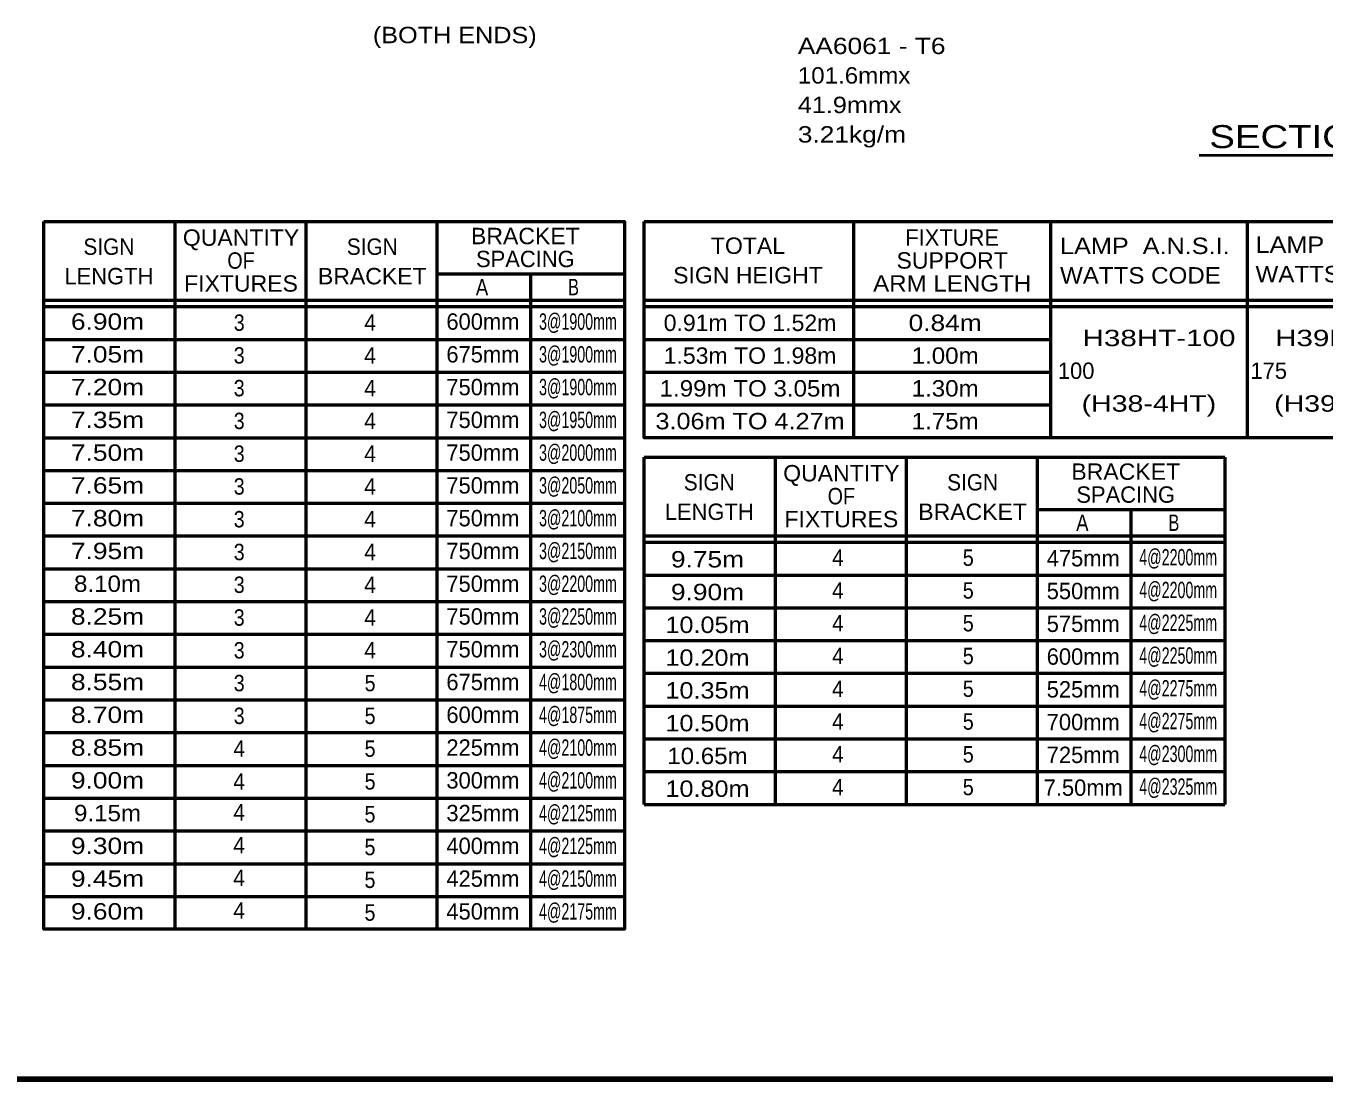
# Model space of a CAD drawing. Extents: x -94 to 762, y -50 to 494.
# Drawn here: x 194.5 to 432, y -38.7 to 154.1 of the extents above; entities that cross this region are included whole.
import ezdxf
from ezdxf.enums import TextEntityAlignment as Align

# ---------------------------------------------------------------- set-up
doc = ezdxf.new("R2010")
doc.units = 0
doc.header["$LTSCALE"] = 1.2
doc.layers.add('1', color=7, linetype='Continuous', lineweight=53)

msp = doc.modelspace()

# ---------------------------------------------------------------- linework, layer by layer
at = {"layer": '1', "lineweight": 40}
msp.add_line((409.176, 130.418), (466.375, 130.418), dxfattribs=at)
at = {"layer": '1'}
for p, q in [((221.733, -11.296), (221.733, 118.303)), ((245.733, -11.296), (245.733, 118.303)), ((269.733, -11.296), (269.733, 118.303)), ((346.014, 78.704), (346.014, 118.303)), ((382.014, 78.704), (382.014, 118.303)), ((418.014, 78.704), (418.014, 118.303)), ((269.733, 108.704), (304.014, 108.704)), ((286.873, -11.296), (286.873, 108.704)), ((197.733, 103.904), (304.014, 103.904)), ((197.733, 102.704), (304.014, 102.704)), ((307.614, 103.904), (490.014, 103.904)), ((307.614, 102.704), (490.014, 102.704)), ((197.733, 96.704), (304.014, 96.704)), ((307.614, 96.704), (382.014, 96.704)), ((197.733, 90.704), (304.014, 90.704)), ((307.614, 90.704), (382.014, 90.704)), ((197.733, 84.704), (304.014, 84.704)), ((307.614, 84.704), (382.014, 84.704)), ((197.733, 78.704), (304.014, 78.704)), ((307.617, 75.162), (379.617, 75.162)), ((307.617, 11.562), (307.617, 75.162)), ((331.617, 11.562), (331.617, 75.162)), ((355.617, 11.562), (355.617, 75.162)), ((379.617, 11.562), (379.617, 75.162)), ((379.617, 75.162), (413.899, 75.162)), ((413.899, 75.162), (413.899, 11.562)), ((197.733, 72.704), (304.014, 72.704)), ((197.733, 66.704), (304.014, 66.704)), ((379.617, 65.562), (413.899, 65.562)), ((396.758, 11.562), (396.758, 65.562)), ((197.733, 60.704), (304.014, 60.704)), ((307.617, 60.762), (379.617, 60.762)), ((307.617, 59.562), (379.617, 59.562)), ((379.617, 60.762), (413.899, 60.762)), ((379.617, 59.562), (413.899, 59.562)), ((197.733, 54.704), (304.014, 54.704)), ((307.617, 53.562), (379.617, 53.562)), ((379.617, 53.562), (413.899, 53.562)), ((197.733, 48.704), (304.014, 48.704)), ((307.617, 47.562), (379.617, 47.562)), ((379.617, 47.562), (413.899, 47.562)), ((197.733, 42.704), (304.014, 42.704)), ((307.617, 41.562), (379.617, 41.562)), ((379.617, 41.562), (413.899, 41.562)), ((197.733, 36.703), (304.014, 36.703)), ((307.617, 35.562), (379.617, 35.562)), ((379.617, 35.562), (413.899, 35.562)), ((197.733, 30.704), (304.014, 30.704)), ((307.617, 29.562), (379.617, 29.562)), ((379.617, 29.562), (413.899, 29.562)), ((197.733, 24.704), (304.014, 24.704)), ((307.617, 23.562), (379.617, 23.562)), ((379.617, 23.562), (413.899, 23.562)), ((197.733, 18.704), (304.014, 18.704)), ((307.617, 17.562), (379.617, 17.562)), ((379.617, 17.562), (413.899, 17.562)), ((197.733, 12.704), (304.014, 12.704)), ((307.617, 11.562), (379.617, 11.562)), ((379.617, 11.562), (413.899, 11.562)), ((197.733, 6.704), (304.014, 6.704)), ((197.733, 0.704), (304.014, 0.704)), ((197.733, -5.296), (304.014, -5.296))]:
    msp.add_line(p, q, dxfattribs=at)
at = {"layer": '1', "lineweight": 158}
msp.add_line((755.402, -38.728), (-36.198, -38.728), dxfattribs=at)
at = {"layer": '1'}
for points in [[(197.733, 118.303), (304.014, 118.303), (304.014, -11.296), (197.733, -11.296)], [(307.614, 118.303), (490.014, 118.303), (490.014, 78.704), (307.614, 78.704)]]:
    msp.add_lwpolyline(points, close=True, dxfattribs=at)

# ---------------------------------------------------------------- texts
for s, height, width, p in [('(BOTH ENDS)', 3, 1.15, (257.948, 150.932)), ('AA6061 - T6', 3, 1.2, (335.73, 148.936)), ('101.6mmx', 3, 1.1, (335.73, 143.536)), ('41.9mmx', 3, 1.15, (335.73, 138.136)), ('3.21kg/m', 3, 1.2, (335.73, 132.736)), ('SECTION "A"-"A"', 4.2, 1.25, (411.053, 131.732)), ('LAMP  A.N.S.I.', 3, 1.15, (383.735, 112.328)), ('LAMP  A.N.S.I.', 3, 1.15, (419.513, 112.547)), ('WATTS CODE', 3, 1.1, (383.735, 106.928)), ('WATTS CODE', 3, 1.1, (419.513, 107.147)), ('A', 3, 0.85, (276.791, 104.758)), ('B', 3, 0.75, (293.678, 104.776)), ('   H38HT-100', 3, 1.35, (383.332, 95.462)), ('   H39KB-175', 3, 1.35, (418.576, 95.462)), ('   (H38-4HT)', 3, 1.3, (383.332, 83.462)), ('   (H39-22KB)', 3, 1.3, (418.576, 83.462)), ('A', 3, 0.85, (386.675, 61.616)), ('B', 3, 0.75, (403.562, 61.634))]:
    msp.add_text(s, height=height, dxfattribs=dict(at, width=width)).set_placement(p)
for s, width, p in [('QUANTITY', 1.05, (233.815, 113.843)), ('BRACKET', 1.05, (285.86, 114.131)), ('SIGN', 0.95, (209.629, 112.184)), ('SIGN', 0.95, (257.842, 112.184)), ('TOTAL', 1.05, (326.609, 112.356)), ('OF', 0.9, (233.815, 109.643)), ('SUPPORT', 1.05, (363.98, 109.656)), ('BRACKET', 1.05, (257.842, 106.784)), ('SIGN HEIGHT', 1.05, (326.609, 106.956)), ('FIXTURES', 1.05, (233.815, 105.443)), ('ARM LENGTH', 1.1, (363.98, 105.456)), ('6.90m', 1.2, (209.377, 98.47)), ('3', 0.9, (233.481, 98.277)), ('4', 0.95, (257.437, 98.277)), ('3@1900mm', 0.65, (295.485, 98.47)), ('0.91m TO 1.52m', 1.05, (326.984, 98.236)), ('0.84m', 1.2, (362.698, 98.236)), ('7.05m', 1.2, (209.377, 92.47)), ('3', 0.9, (233.481, 92.277)), ('4', 0.95, (257.437, 92.277)), ('3@1900mm', 0.65, (295.485, 92.47)), ('1.53m TO 1.98m', 1.05, (326.984, 92.236)), ('1.00m', 1.1, (362.698, 92.236)), ('7.20m', 1.2, (209.377, 86.47)), ('3', 0.9, (233.481, 86.277)), ('4', 0.95, (257.437, 86.277)), ('3@1900mm', 0.65, (295.485, 86.47)), ('1.99m TO 3.05m', 1.1, (326.984, 86.236)), ('1.30m', 1.1, (362.698, 86.236)), ('7.35m', 1.2, (209.377, 80.47)), ('3', 0.9, (233.481, 80.277)), ('4', 0.95, (257.437, 80.277)), ('3@1950mm', 0.65, (295.485, 80.47)), ('3.06m TO 4.27m', 1.15, (326.984, 80.236)), ('1.75m', 1.1, (362.698, 80.236)), ('7.50m', 1.2, (209.377, 74.47)), ('3', 0.9, (233.481, 74.277)), ('4', 0.95, (257.437, 74.277)), ('3@2000mm', 0.65, (295.485, 74.47)), ('QUANTITY', 1.05, (343.7, 70.701)), ('BRACKET', 1.05, (395.745, 70.989)), ('7.65m', 1.2, (209.377, 68.47)), ('3', 0.9, (233.481, 68.277)), ('3@2050mm', 0.65, (295.485, 68.47)), ('SIGN', 0.95, (319.514, 69.042)), ('SIGN', 0.95, (367.726, 69.042)), ('4', 0.95, (257.437, 68.277)), ('OF', 0.9, (343.7, 66.501)), ('BRACKET', 1.05, (367.726, 63.642)), ('7.80m', 1.2, (209.377, 62.47)), ('3', 0.9, (233.481, 62.277)), ('4', 0.95, (257.437, 62.277)), ('3@2100mm', 0.65, (295.485, 62.47)), ('FIXTURES', 1.05, (343.7, 62.301)), ('7.95m', 1.2, (209.377, 56.47)), ('3@2150mm', 0.65, (295.485, 56.47)), ('3', 0.9, (233.481, 56.277)), ('4', 0.95, (257.437, 56.277)), ('9.75m', 1.2, (319.195, 54.942)), ('4', 0.95, (343.062, 55.237)), ('5', 0.9, (366.93, 55.237)), ('4@2200mm', 0.65, (405.358, 55.322)), ('8.10m', 1.1, (209.377, 50.47)), ('3', 0.9, (233.481, 50.277)), ('4', 0.95, (257.437, 50.277)), ('3@2200mm', 0.65, (295.485, 50.47)), ('4@2200mm', 0.65, (405.358, 49.322)), ('9.90m', 1.2, (319.195, 48.942)), ('4', 0.95, (343.062, 49.237)), ('5', 0.9, (366.93, 49.237)), ('3@2250mm', 0.65, (295.485, 44.47)), ('8.25m', 1.2, (209.377, 44.47)), ('3', 0.9, (233.481, 44.277)), ('4', 0.95, (257.437, 44.277)), ('10.05m', 1.15, (319.195, 42.942)), ('4', 0.95, (343.062, 43.237)), ('5', 0.9, (366.93, 43.237)), ('4@2225mm', 0.65, (405.358, 43.322)), ('8.40m', 1.2, (209.377, 38.47)), ('3', 0.9, (233.481, 38.277)), ('4', 0.95, (257.437, 38.277)), ('3@2300mm', 0.65, (295.485, 38.47)), ('4@2250mm', 0.65, (405.358, 37.322)), ('10.20m', 1.15, (319.195, 36.942)), ('4', 0.95, (343.062, 37.237)), ('5', 0.9, (366.93, 37.237)), ('8.55m', 1.2, (209.377, 32.47)), ('3', 0.9, (233.481, 32.277)), ('5', 0.9, (257.437, 32.277)), ('4@1800mm', 0.65, (295.485, 32.47)), ('10.35m', 1.15, (319.195, 30.942)), ('4', 0.95, (343.062, 31.237)), ('5', 0.9, (366.93, 31.237)), ('4@2275mm', 0.65, (405.358, 31.322)), ('8.70m', 1.2, (209.377, 26.47)), ('3', 0.9, (233.481, 26.277)), ('5', 0.9, (257.437, 26.277)), ('4@1875mm', 0.65, (295.485, 26.47)), ('10.50m', 1.15, (319.195, 24.942)), ('4', 0.95, (343.062, 25.237)), ('5', 0.9, (366.93, 25.237)), ('4@2275mm', 0.65, (405.358, 25.322)), ('8.85m', 1.2, (209.377, 20.47)), ('4', 0.95, (233.481, 20.277)), ('5', 0.9, (257.437, 20.277)), ('4@2100mm', 0.65, (295.485, 20.47)), ('10.65m', 1.1, (319.195, 18.942)), ('4', 0.95, (343.062, 19.237)), ('5', 0.9, (366.93, 19.237)), ('4@2300mm', 0.65, (405.358, 19.322)), ('9.00m', 1.2, (209.377, 14.47)), ('4', 0.95, (233.481, 14.277)), ('5', 0.9, (257.437, 14.277)), ('4@2100mm', 0.65, (295.485, 14.47)), ('10.80m', 1.15, (319.195, 12.942)), ('4', 0.95, (343.062, 13.237)), ('5', 0.9, (366.93, 13.237)), ('4@2325mm', 0.65, (405.358, 13.322)), ('9.15m', 1.1, (209.377, 8.47)), ('4', 0.95, (233.464, 8.611)), ('5', 0.9, (257.42, 8.257)), ('4@2125mm', 0.65, (295.485, 8.47)), ('9.30m', 1.2, (209.377, 2.47)), ('4', 0.95, (233.464, 2.611)), ('5', 0.9, (257.42, 2.256)), ('4@2125mm', 0.65, (295.485, 2.47)), ('9.45m', 1.2, (209.377, -3.53)), ('4', 0.95, (233.464, -3.389)), ('5', 0.9, (257.42, -3.744)), ('4@2150mm', 0.65, (295.485, -3.53)), ('9.60m', 1.2, (209.377, -9.53)), ('4', 0.95, (233.464, -9.389)), ('5', 0.9, (257.42, -9.744)), ('4@2175mm', 0.65, (295.485, -9.53))]:
    msp.add_text(s, height=3, dxfattribs=dict(at, width=width)).set_placement(p, align=Align.CENTER)
for s, p in [('FIXTURE', (363.98, 113.856)), ('SPACING', (285.86, 109.931)), ('LENGTH', (209.629, 106.784)), ('600mm', (278.091, 98.47)), ('675mm', (278.091, 92.47)), ('750mm', (278.091, 86.47)), ('750mm', (278.091, 80.47)), ('750mm', (278.091, 74.47)), ('750mm', (278.091, 68.47)), ('SPACING', (395.745, 66.788)), ('LENGTH', (319.514, 63.642)), ('750mm', (278.091, 62.47)), ('750mm', (278.091, 56.47)), ('475mm', (387.976, 55.132)), ('750mm', (278.091, 50.47)), ('550mm', (387.976, 49.132)), ('750mm', (278.091, 44.47)), ('575mm', (387.976, 43.132)), ('750mm', (278.091, 38.47)), ('600mm', (387.976, 37.132)), ('675mm', (278.091, 32.47)), ('525mm', (387.976, 31.132)), ('600mm', (278.091, 26.47)), ('700mm', (387.976, 25.132)), ('225mm', (278.091, 20.47)), ('725mm', (387.976, 19.132)), ('300mm', (278.091, 14.47)), ('7.50mm', (387.976, 13.132)), ('325mm', (278.091, 8.47)), ('400mm', (278.091, 2.47)), ('425mm', (278.091, -3.53)), ('450mm', (278.091, -9.53))]:
    msp.add_text(s, height=3, dxfattribs=at).set_placement(p, align=Align.CENTER)
for s, p in [('100', (383.332, 89.462)), ('175', (418.576, 89.462))]:
    msp.add_text(s, height=3, dxfattribs=at).set_placement(p)

doc.saveas('drawing.dxf')
